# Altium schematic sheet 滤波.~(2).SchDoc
size A4
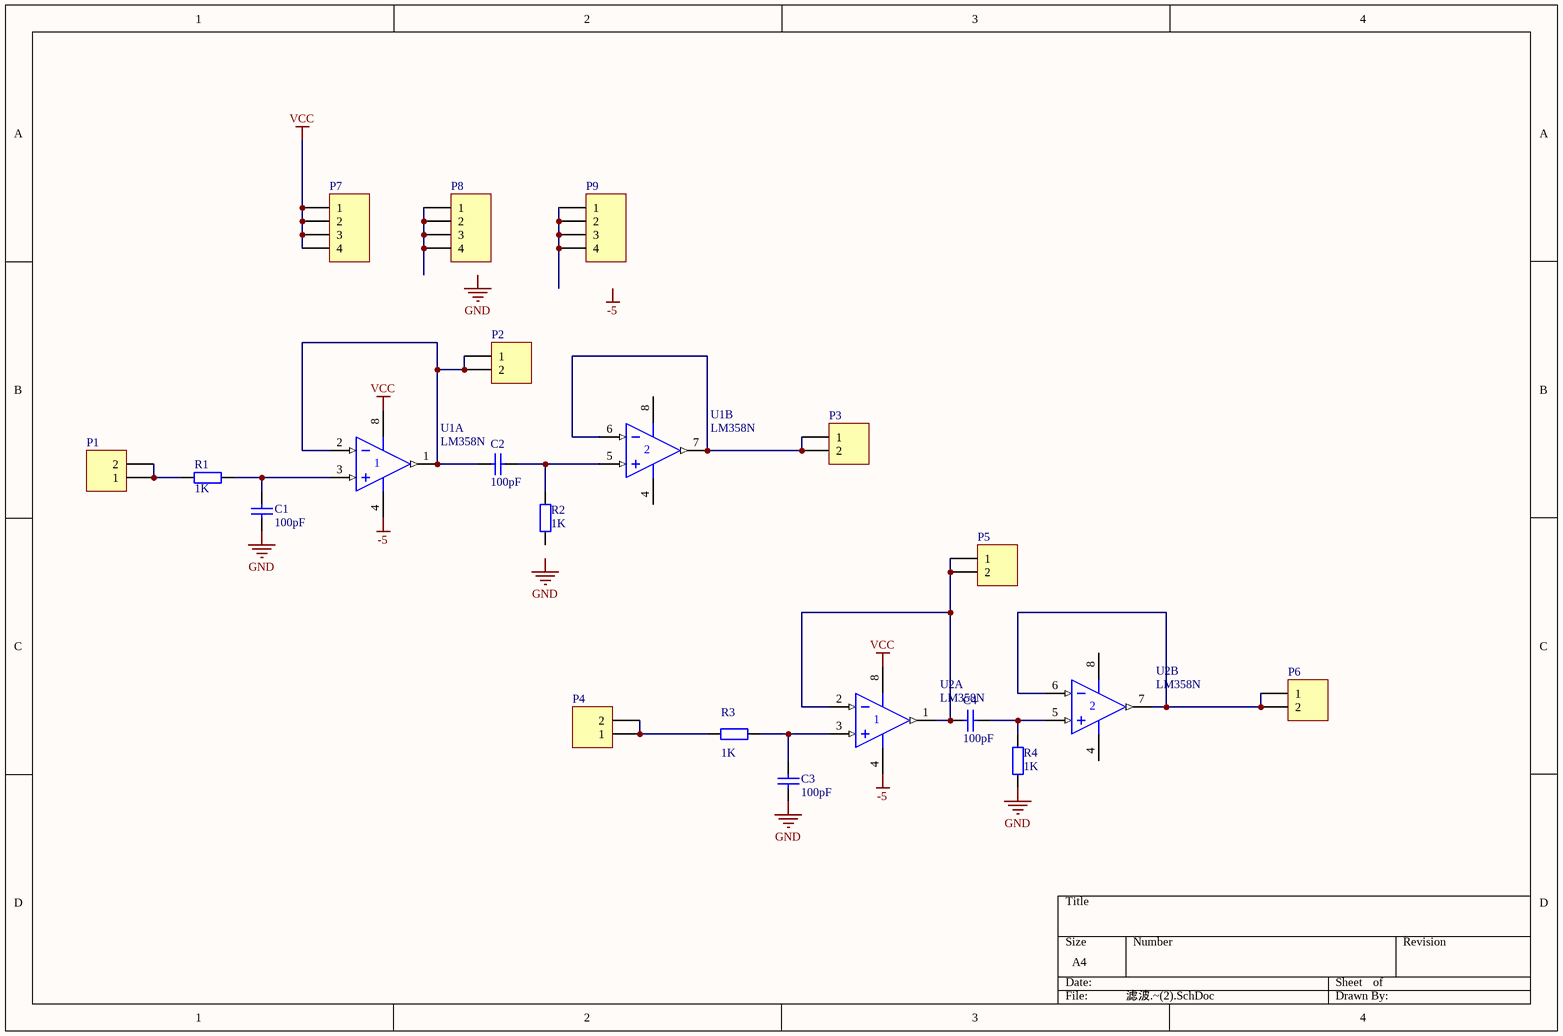
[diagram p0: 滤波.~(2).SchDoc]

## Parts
C1  value 100pF  [CAPR2.54-5.1x3.2]  (hidden comment: Cap)
C2  value 100pF  [CAPR2.54-5.1x3.2]  (hidden comment: Cap)
C3  value 100pF  [CAPR2.54-5.1x3.2]  (hidden comment: Cap)
C4  value 100pF  [CAPR2.54-5.1x3.2]  (hidden comment: Cap)
P1  Header 2  [HDR1X2]  (value not drawn)
P2  Header 2  [HDR1X2]  (value not drawn)
P3  Header 2  [HDR1X2]  (value not drawn)
P4  Header 2  [HDR1X2]  (value not drawn)
P5  Header 2  [HDR1X2]  (value not drawn)
P6  Header 2  [HDR1X2]  (value not drawn)
P7  Header 4  [HDR1X4]  (value not drawn)
P8  Header 4  [HDR1X4]  (value not drawn)
P9  Header 4  [HDR1X4]  (value not drawn)
R1  value 1K  [AXIAL-0.4]  (hidden comment: Res2)
R2  value 1K  [AXIAL-0.4]  (hidden comment: Res2)
R3  value 1K  [AXIAL-0.4]  (hidden comment: Res2)
R4  value 1K  [AXIAL-0.4]  (hidden comment: Res2)
U1  LM358N  [626-05]  (parts A,B of 2)
U2  LM358N  [626-05]  (parts A,B of 2)

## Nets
-5: U1.4(V-) U2.4(V-)
GND: C1.1 C3.1 R4.1
VCC: P7.1 P7.2 P7.3 P7.4 U1.8(V+) U2.8(V+)
NetC1_2: C1.2 R1.2 U1.3(IN+)
NetC2_1: C2.1 P2.1 P2.2 U1.1(OUT) U1.2(IN-)
NetC2_2: C2.2 R2.2 U1.5(IN+)
NetC3_2: C3.2 R3.2 U2.3(IN+)
NetC4_1: C4.1 P5.1 P5.2 U2.1(OUT) U2.2(IN-)
NetC4_2: C4.2 R4.2 U2.5(IN+)
NetP1_1: P1.1 P1.2 R1.1
NetP3_1: P3.1 P3.2 U1.6(IN-) U1.7(OUT)
NetP4_1: P4.1 P4.2 R3.1
NetP6_1: P6.1 P6.2 U2.6(IN-) U2.7(OUT)
NetP8_1: P8.1 P8.2 P8.3 P8.4
NetP9_1: P9.1 P9.2 P9.3 P9.4

Not connected (* = marked no-connect by the designer): R2 1

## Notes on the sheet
- Labels drawn without touching a wire or pin: -5, GND

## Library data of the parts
C1-C4 = Cap: Capacitor
P1-P6 = Header 2: Header, 2-Pin
P7-P9 = Header 4: Header, 4-Pin
R1-R4 = Res2: Resistor
U1 U2 = LM358N: Dual Low-Power Operational Amplifier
